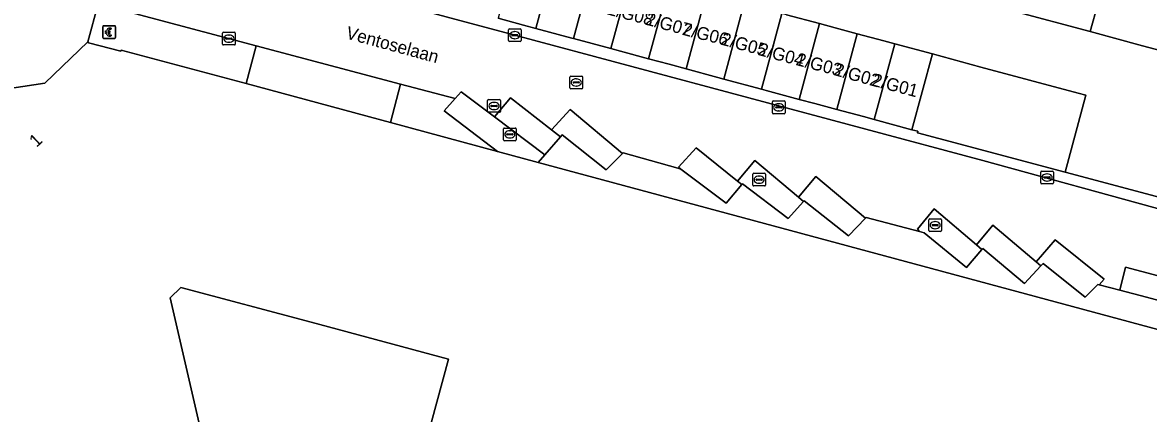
# Model space of a CAD drawing. Extents: x 160675 to 161153, y 383241 to 383714.
# Drawn here: x 160731.8 to 160820, y 383533.4 to 383564 of the extents above; entities that cross this region are included whole.
import ezdxf

# ---------------------------------------------------------------- set-up
doc = ezdxf.new("R2010")
doc.units = 0
for name, color, linetype in [('IMGEO_Betaalautomaat', 7, 'Continuous'), ('IMGEO_Erf', 7, 'Continuous'), ('IMGEO_Kolk', 7, 'Continuous'), ('IMGEO_Openbare_ruimte_label', 7, 'Continuous'), ('IMGEO_Pand', 7, 'Continuous'), ('IMGEO_Pand_nummerreeks', 7, 'Continuous'), ('IMGEO_Parkeervlak_open', 7, 'Continuous'), ('IMGEO_Rijbaan_lokaal_open', 7, 'Continuous'), ('IMGEO_Rioolput', 7, 'Continuous'), ('IMGEO_Voetpad_gesloten', 7, 'Continuous'), ('IMGEO_Voetpad_open', 7, 'Continuous')]:
    doc.layers.add(name, color=color, linetype=linetype)

msp = doc.modelspace()

# ---------------------------------------------------------------- linework, layer by layer
at = {"layer": 'IMGEO_Betaalautomaat'}
for p, q in [((160738.042, 383562.848), (160738.042, 383563.689)), ((160738.042, 383563.689), (160738.042, 383562.848)), ((160738.117, 383563.772), (160738.958, 383563.772)), ((160738.958, 383563.772), (160738.117, 383563.772)), ((160738.704, 383563.577), (160738.687, 383563.477)), ((160739.041, 383563.698), (160739.041, 383562.857)), ((160739.041, 383562.857), (160739.041, 383563.698)), ((160738.967, 383562.773), (160738.126, 383562.773)), ((160738.126, 383562.773), (160738.967, 383562.773)), ((160738.325, 383563.236), (160738.325, 383563.304)), ((160738.446, 383563.304), (160738.446, 383563.236)), ((160738.691, 383563.071), (160738.713, 383562.984))]:
    msp.add_line(p, q, dxfattribs=at)
for points in [[(160738.325, 383563.304), (160738.256, 383563.304), (160738.256, 383563.373), (160738.335, 383563.373)], [(160738.33, 383563.167), (160738.256, 383563.167), (160738.256, 383563.236), (160738.325, 383563.236)], [(160738.457, 383563.373), (160738.604, 383563.373), (160738.604, 383563.304), (160738.446, 383563.304)], [(160738.446, 383563.236), (160738.604, 383563.236), (160738.604, 383563.167), (160738.46, 383563.167)]]:
    msp.add_lwpolyline(points, dxfattribs=at)
for centre, radius, start, end in [((160738.12, 383563.695), 0.0779, 92.4484, 184.28452), ((160738.12, 383563.695), 0.0779, 92.4484, 184.28452), ((160738.618, 383563.297), 0.293, 73.01398, 165.01395), ((160738.964, 383563.695), 0.0779, 2.4484, 94.28452), ((160738.964, 383563.695), 0.0779, 2.4484, 94.28452), ((160738.12, 383562.851), 0.0779, 182.4484, 274.28452), ((160738.12, 383562.851), 0.0779, 182.4484, 274.28452), ((160738.591, 383563.222), 0.267, 191.80956, 297.03891), ((160738.624, 383563.31), 0.179, 69.32359, 159.56827), ((160738.624, 383563.237), 0.179, 202.76249, 291.86925), ((160738.964, 383562.851), 0.0779, 272.4484, 4.28452), ((160738.964, 383562.851), 0.0779, 272.4484, 4.28452)]:
    msp.add_arc(centre, radius, start, end, dxfattribs=at)
at = {"layer": 'IMGEO_Erf'}
for points in [[(160791.615, 383564.635), (160794.187, 383563.942), (160795.419, 383563.61), (160797.134, 383563.148), (160799.224, 383562.585), (160800.081, 383562.354), (160803.028, 383561.56), (160806.833, 383560.536), (160810.637, 383559.511), (160814.441, 383558.486), (160815.054, 383558.321), (160813.434, 383552.307), (160835.666, 383546.367)], [(160821.47, 383561.669), (160819.477, 383562.206), (160815.386, 383563.308), (160809.303, 383564.947)]]:
    msp.add_lwpolyline(points, dxfattribs=at)
msp.add_lwpolyline([(160765.12, 383537.659), (160754.382, 383540.56), (160744.154, 383543.281), (160743.335, 383542.457), (160748.196, 383521.306), (160756.534, 383523.204), (160762.882, 383529.378)], close=True, dxfattribs=at)
at = {"layer": 'IMGEO_Kolk'}
for p, q in [((160769.896, 383563.534), (160770.748, 383563.534)), ((160747.424, 383562.339), (160747.424, 383563.191)), ((160747.499, 383563.265), (160748.351, 383563.265)), ((160747.683, 383562.759), (160747.683, 383562.771)), ((160748.121, 383562.722), (160747.723, 383562.722)), ((160747.726, 383562.808), (160748.124, 383562.808)), ((160747.912, 383563.045), (160747.937, 383563.045)), ((160748.167, 383562.771), (160748.167, 383562.759)), ((160748.425, 383563.191), (160748.425, 383562.339)), ((160769.821, 383562.608), (160769.821, 383563.46)), ((160770.08, 383563.028), (160770.08, 383563.04)), ((160770.518, 383562.991), (160770.12, 383562.991)), ((160770.123, 383563.077), (160770.521, 383563.077)), ((160770.332, 383562.754), (160770.307, 383562.754)), ((160770.309, 383563.314), (160770.334, 383563.314)), ((160770.564, 383563.04), (160770.564, 383563.028)), ((160770.822, 383563.46), (160770.822, 383562.608)), ((160748.351, 383562.265), (160747.499, 383562.265)), ((160747.935, 383562.485), (160747.91, 383562.485)), ((160770.748, 383562.534), (160769.896, 383562.534)), ((160768.194, 383557.064), (160768.194, 383557.916)), ((160768.269, 383557.99), (160769.121, 383557.99)), ((160768.453, 383557.484), (160768.453, 383557.496)), ((160768.891, 383557.447), (160768.493, 383557.447)), ((160768.496, 383557.533), (160768.894, 383557.533)), ((160768.682, 383557.77), (160768.707, 383557.77)), ((160768.937, 383557.496), (160768.937, 383557.484)), ((160769.195, 383557.916), (160769.195, 383557.064)), ((160790.496, 383556.952), (160790.496, 383557.804)), ((160790.571, 383557.878), (160791.423, 383557.878)), ((160790.755, 383557.372), (160790.755, 383557.384)), ((160791.193, 383557.335), (160790.795, 383557.335)), ((160790.798, 383557.421), (160791.196, 383557.421)), ((160790.984, 383557.658), (160791.009, 383557.658)), ((160791.239, 383557.384), (160791.239, 383557.372)), ((160791.497, 383557.804), (160791.497, 383556.952)), ((160769.121, 383556.99), (160768.269, 383556.99)), ((160768.705, 383557.21), (160768.68, 383557.21)), ((160791.423, 383556.878), (160790.571, 383556.878)), ((160791.007, 383557.098), (160790.982, 383557.098)), ((160788.957, 383551.294), (160788.957, 383552.146)), ((160789.032, 383552.22), (160789.884, 383552.22)), ((160789.958, 383552.146), (160789.958, 383551.294)), ((160811.514, 383551.462), (160811.514, 383552.314)), ((160811.589, 383552.388), (160812.441, 383552.388)), ((160812.002, 383552.168), (160812.027, 383552.168)), ((160812.515, 383552.314), (160812.515, 383551.462)), ((160789.884, 383551.22), (160789.032, 383551.22)), ((160789.216, 383551.714), (160789.216, 383551.726)), ((160789.654, 383551.677), (160789.256, 383551.677)), ((160789.259, 383551.763), (160789.657, 383551.763)), ((160789.468, 383551.44), (160789.443, 383551.44)), ((160789.445, 383552), (160789.47, 383552)), ((160789.7, 383551.726), (160789.7, 383551.714)), ((160812.441, 383551.388), (160811.589, 383551.388)), ((160811.773, 383551.882), (160811.773, 383551.894)), ((160812.211, 383551.845), (160811.813, 383551.845)), ((160811.816, 383551.931), (160812.214, 383551.931)), ((160812.025, 383551.608), (160812, 383551.608)), ((160812.257, 383551.894), (160812.257, 383551.882)), ((160802.745, 383547.728), (160802.745, 383548.58)), ((160802.82, 383548.654), (160803.672, 383548.654)), ((160803.746, 383548.58), (160803.746, 383547.728)), ((160803.672, 383547.654), (160802.82, 383547.654)), ((160803.004, 383548.148), (160803.004, 383548.16)), ((160803.442, 383548.111), (160803.044, 383548.111)), ((160803.047, 383548.197), (160803.445, 383548.197)), ((160803.256, 383547.874), (160803.231, 383547.874)), ((160803.233, 383548.434), (160803.258, 383548.434)), ((160803.488, 383548.16), (160803.488, 383548.148))]:
    msp.add_line(p, q, dxfattribs=at)
for points in [[(160769.896, 383563.534), (160770.748, 383563.534)], [(160747.424, 383562.339), (160747.424, 383563.191)], [(160747.499, 383563.265), (160748.351, 383563.265)], [(160748.425, 383563.191), (160748.425, 383562.339)], [(160769.821, 383562.608), (160769.821, 383563.46)], [(160770.822, 383563.46), (160770.822, 383562.608)], [(160748.351, 383562.265), (160747.499, 383562.265)], [(160770.748, 383562.534), (160769.896, 383562.534)], [(160768.194, 383557.064), (160768.194, 383557.916)], [(160768.269, 383557.99), (160769.121, 383557.99)], [(160769.195, 383557.916), (160769.195, 383557.064)], [(160790.496, 383556.952), (160790.496, 383557.804)], [(160790.571, 383557.878), (160791.423, 383557.878)], [(160791.497, 383557.804), (160791.497, 383556.952)], [(160769.121, 383556.99), (160768.269, 383556.99)], [(160791.423, 383556.878), (160790.571, 383556.878)], [(160788.957, 383551.294), (160788.957, 383552.146)], [(160789.032, 383552.22), (160789.884, 383552.22)], [(160789.958, 383552.146), (160789.958, 383551.294)], [(160811.514, 383551.462), (160811.514, 383552.314)], [(160811.589, 383552.388), (160812.441, 383552.388)], [(160812.515, 383552.314), (160812.515, 383551.462)], [(160789.884, 383551.22), (160789.032, 383551.22)], [(160812.441, 383551.388), (160811.589, 383551.388)], [(160802.745, 383547.728), (160802.745, 383548.58)], [(160802.82, 383548.654), (160803.672, 383548.654)], [(160803.746, 383548.58), (160803.746, 383547.728)], [(160803.672, 383547.654), (160802.82, 383547.654)]]:
    msp.add_lwpolyline(points, dxfattribs=at)
for centre, radius, start, end in [((160769.898, 383563.458), 0.0765, 91.55205, 178.44795), ((160769.898, 383563.458), 0.0765, 91.55205, 178.44795), ((160770.746, 383563.458), 0.0765, 1.55205, 88.44795), ((160770.746, 383563.458), 0.0765, 1.55205, 88.44795), ((160747.501, 383563.189), 0.0765, 91.55205, 178.44795), ((160747.501, 383563.189), 0.0765, 91.55205, 178.44795), ((160747.723, 383562.768), 0.0403, 85.87752, 175.75265), ((160747.72, 383562.758), 0.0366, 178.93798, 274.71019), ((160748.124, 383562.765), 0.043, 264.86636, 352.45326), ((160748.128, 383562.77), 0.0386, 1.73085, 96.63898), ((160748.349, 383563.189), 0.0765, 1.55205, 88.44795), ((160748.349, 383563.189), 0.0765, 1.55205, 88.44795), ((160770.12, 383563.037), 0.0403, 85.87752, 175.75265), ((160770.117, 383563.027), 0.0366, 178.93798, 274.71019), ((160770.521, 383563.034), 0.043, 264.86636, 352.45326), ((160770.525, 383563.039), 0.0386, 1.73085, 96.63898), ((160747.501, 383562.341), 0.0765, 181.55205, 268.44795), ((160747.501, 383562.341), 0.0765, 181.55205, 268.44795), ((160748.349, 383562.341), 0.0765, 271.55205, 358.44795), ((160748.349, 383562.341), 0.0765, 271.55205, 358.44795), ((160769.898, 383562.61), 0.0765, 181.55205, 268.44795), ((160769.898, 383562.61), 0.0765, 181.55205, 268.44795), ((160770.746, 383562.61), 0.0765, 271.55205, 358.44795), ((160770.746, 383562.61), 0.0765, 271.55205, 358.44795), ((160768.271, 383557.914), 0.0765, 91.55205, 178.44795), ((160768.271, 383557.914), 0.0765, 91.55205, 178.44795), ((160768.493, 383557.493), 0.0403, 85.87752, 175.75265), ((160768.49, 383557.483), 0.0366, 178.93798, 274.71019), ((160768.894, 383557.49), 0.043, 264.86636, 352.45326), ((160768.898, 383557.495), 0.0386, 1.73085, 96.63898), ((160769.119, 383557.914), 0.0765, 1.55205, 88.44795), ((160769.119, 383557.914), 0.0765, 1.55205, 88.44795), ((160790.573, 383557.802), 0.0765, 91.55205, 178.44795), ((160790.573, 383557.802), 0.0765, 91.55205, 178.44795), ((160790.795, 383557.381), 0.0403, 85.87752, 175.75265), ((160790.792, 383557.371), 0.0366, 178.93798, 274.71019), ((160791.196, 383557.378), 0.043, 264.86636, 352.45326), ((160791.2, 383557.383), 0.0386, 1.73085, 96.63898), ((160791.421, 383557.802), 0.0765, 1.55205, 88.44795), ((160791.421, 383557.802), 0.0765, 1.55205, 88.44795), ((160768.271, 383557.066), 0.0765, 181.55205, 268.44795), ((160768.271, 383557.066), 0.0765, 181.55205, 268.44795), ((160769.119, 383557.066), 0.0765, 271.55205, 358.44795), ((160769.119, 383557.066), 0.0765, 271.55205, 358.44795), ((160790.573, 383556.954), 0.0765, 181.55205, 268.44795), ((160790.573, 383556.954), 0.0765, 181.55205, 268.44795), ((160791.421, 383556.954), 0.0765, 271.55205, 358.44795), ((160791.421, 383556.954), 0.0765, 271.55205, 358.44795), ((160789.034, 383552.144), 0.0765, 91.55205, 178.44795), ((160789.034, 383552.144), 0.0765, 91.55205, 178.44795), ((160789.882, 383552.144), 0.0765, 1.55205, 88.44795), ((160789.882, 383552.144), 0.0765, 1.55205, 88.44795), ((160811.591, 383552.312), 0.0765, 91.55205, 178.44795), ((160811.591, 383552.312), 0.0765, 91.55205, 178.44795), ((160812.439, 383552.312), 0.0765, 1.55205, 88.44795), ((160812.439, 383552.312), 0.0765, 1.55205, 88.44795), ((160789.034, 383551.296), 0.0765, 181.55205, 268.44795), ((160789.034, 383551.296), 0.0765, 181.55205, 268.44795), ((160789.256, 383551.723), 0.0403, 85.87752, 175.75265), ((160789.253, 383551.713), 0.0366, 178.93798, 274.71019), ((160789.657, 383551.72), 0.043, 264.86636, 352.45326), ((160789.661, 383551.725), 0.0386, 1.73085, 96.63898), ((160789.882, 383551.296), 0.0765, 271.55205, 358.44795), ((160789.882, 383551.296), 0.0765, 271.55205, 358.44795), ((160811.591, 383551.464), 0.0765, 181.55205, 268.44795), ((160811.591, 383551.464), 0.0765, 181.55205, 268.44795), ((160811.813, 383551.891), 0.0403, 85.87752, 175.75265), ((160811.81, 383551.881), 0.0366, 178.93798, 274.71019), ((160812.214, 383551.888), 0.043, 264.86636, 352.45326), ((160812.218, 383551.893), 0.0386, 1.73085, 96.63898), ((160812.439, 383551.464), 0.0765, 271.55205, 358.44795), ((160812.439, 383551.464), 0.0765, 271.55205, 358.44795), ((160802.822, 383548.578), 0.0765, 91.55205, 178.44795), ((160802.822, 383548.578), 0.0765, 91.55205, 178.44795), ((160803.67, 383548.578), 0.0765, 1.55205, 88.44795), ((160803.67, 383548.578), 0.0765, 1.55205, 88.44795), ((160802.822, 383547.73), 0.0765, 181.55205, 268.44795), ((160802.822, 383547.73), 0.0765, 181.55205, 268.44795), ((160803.044, 383548.157), 0.0403, 85.87752, 175.75265), ((160803.041, 383548.147), 0.0366, 178.93798, 274.71019), ((160803.445, 383548.154), 0.043, 264.86636, 352.45326), ((160803.449, 383548.159), 0.0386, 1.73085, 96.63898), ((160803.67, 383547.73), 0.0765, 271.55205, 358.44795), ((160803.67, 383547.73), 0.0765, 271.55205, 358.44795)]:
    msp.add_arc(centre, radius, start, end, dxfattribs=at)
for centre, major_axis, ratio, start_param, end_param in [((160747.911, 383562.765), (-0.387, 0.002), 0.722429, 4.712389, 7.853982), ((160747.936, 383562.765), (-0.39, 0.002), 0.717154, 1.570796, 4.712389), ((160770.308, 383563.034), (-0.387, 0.002), 0.722429, 4.712389, 7.853982), ((160770.333, 383563.034), (-0.39, 0.002), 0.717154, 1.570796, 4.712389), ((160768.681, 383557.49), (-0.387, 0.002), 0.722429, 4.712389, 7.853982), ((160768.706, 383557.49), (-0.39, 0.002), 0.717154, 1.570796, 4.712389), ((160790.983, 383557.378), (-0.387, 0.002), 0.722429, 4.712389, 7.853982), ((160791.008, 383557.378), (-0.39, 0.002), 0.717154, 1.570796, 4.712389), ((160812.001, 383551.888), (-0.387, 0.002), 0.722429, 4.712389, 7.853982), ((160812.026, 383551.888), (-0.39, 0.002), 0.717154, 1.570796, 4.712389), ((160789.444, 383551.72), (-0.387, 0.002), 0.722429, 4.712389, 7.853982), ((160789.469, 383551.72), (-0.39, 0.002), 0.717154, 1.570796, 4.712389), ((160803.232, 383548.154), (-0.387, 0.002), 0.722429, 4.712389, 7.853982), ((160803.257, 383548.154), (-0.39, 0.002), 0.717154, 1.570796, 4.712389)]:
    msp.add_ellipse(centre, major_axis=major_axis, ratio=ratio, start_param=start_param, end_param=end_param, dxfattribs=at)
at = {"layer": 'IMGEO_Pand'}
for points in [[(160815.386, 383563.308), (160818.982, 383576.181), (160812.898, 383577.819), (160809.303, 383564.947)], [(160819.477, 383562.206), (160821.47, 383561.669), (160825.065, 383574.542), (160818.982, 383576.181), (160815.386, 383563.308)], [(160773.558, 383569.498), (160772.593, 383569.758), (160770.612, 383570.292), (160769.014, 383564.36), (160770.995, 383563.826), (160771.961, 383563.566)], [(160773.558, 383569.498), (160771.961, 383563.566), (160774.799, 383562.801), (160774.907, 383562.772), (160776.505, 383568.704), (160776.397, 383568.734)], [(160779.452, 383567.911), (160776.505, 383568.704), (160774.907, 383562.772), (160777.854, 383561.978)], [(160779.452, 383567.911), (160777.854, 383561.978), (160778.604, 383561.776), (160780.801, 383561.184), (160782.399, 383567.117), (160780.202, 383567.709)], [(160783.748, 383560.389), (160785.346, 383566.323), (160784.006, 383566.684), (160782.399, 383567.117), (160780.801, 383561.184), (160782.408, 383560.751)], [(160788.293, 383565.529), (160787.811, 383565.659), (160785.346, 383566.323), (160783.748, 383560.389), (160786.212, 383559.725), (160786.695, 383559.595)], [(160788.293, 383565.529), (160786.695, 383559.595), (160789.642, 383558.801), (160791.24, 383564.736)], [(160791.24, 383564.736), (160789.642, 383558.801), (160790.016, 383558.7), (160792.589, 383558.007), (160794.187, 383563.942), (160791.615, 383564.635)], [(160795.536, 383557.213), (160797.134, 383563.148), (160795.419, 383563.61), (160794.187, 383563.942), (160792.589, 383558.007), (160793.821, 383557.675)], [(160795.536, 383557.213), (160797.625, 383556.65), (160798.482, 383556.419), (160800.081, 383562.354), (160799.224, 383562.585), (160797.134, 383563.148)], [(160801.429, 383555.625), (160803.028, 383561.56), (160800.081, 383562.354), (160798.482, 383556.419)], [(160815.054, 383558.321), (160814.441, 383558.486), (160810.637, 383559.511), (160806.833, 383560.536), (160803.028, 383561.56), (160801.429, 383555.625), (160801.89, 383555.501), (160801.862, 383555.394), (160805.207, 383554.502), (160809.014, 383553.486), (160813.434, 383552.307)], [(160762.882, 383529.378), (160756.534, 383523.204), (160748.196, 383521.306), (160743.335, 383542.457), (160744.154, 383543.281), (160754.382, 383540.56), (160765.12, 383537.659)]]:
    msp.add_lwpolyline(points, close=True, dxfattribs=at)
msp.add_lwpolyline([(160824.365, 383538.998), (160772.161, 383553.067), (160768.978, 383553.925), (160760.578, 383556.188), (160749.27, 383559.236), (160739.499, 383561.869), (160739.458, 383561.769), (160736.936, 383562.441), (160736.867, 383562.513), (160734.183, 383559.937), (160733.494, 383559.276), (160728.647, 383558.534), (160727.771, 383553.734), (160724.44, 383550.502), (160724.51, 383550.431), (160725.086, 383547.856), (160724.989, 383547.833), (160725.173, 383547.028), (160737.721, 383492.328)], dxfattribs=at)
at = {"layer": 'IMGEO_Parkeervlak_open'}
for points in [[(160765.643, 383558.073), (160761.377, 383559.203), (160760.578, 383556.188), (160768.978, 383553.925), (160764.787, 383557.113)], [(160768.731, 383556.624), (160766.112, 383558.599), (160765.643, 383558.073), (160764.787, 383557.113), (160768.978, 383553.925), (160772.161, 383553.067), (160772.669, 383553.654)], [(160768.731, 383556.624), (160772.669, 383553.654), (160773.903, 383555.08), (160773.2, 383555.625), (160769.987, 383558.116)], [(160773.2, 383555.625), (160773.903, 383555.08), (160774.032, 383555.228), (160777.477, 383552.475), (160778.768, 383553.77), (160774.65, 383557.216)], [(160783.322, 383552.547), (160786.884, 383549.861), (160788.11, 383551.327), (160787.775, 383551.597), (160784.524, 383554.209), (160783.154, 383552.689)], [(160792.94, 383550.004), (160792.542, 383550.339), (160789.123, 383553.211), (160787.775, 383551.597), (160788.11, 383551.327), (160788.159, 383551.385), (160791.74, 383548.675)], [(160792.542, 383550.339), (160792.94, 383550.004), (160792.987, 383550.057), (160796.452, 383547.324), (160797.791, 383548.706), (160793.905, 383551.971)], [(160802.032, 383547.656), (160802.399, 383547.561), (160805.699, 383544.831), (160806.916, 383546.239), (160806.478, 383546.613), (160803.172, 383549.44), (160801.852, 383547.834)], [(160806.478, 383546.613), (160806.916, 383546.239), (160806.981, 383546.315), (160810.235, 383543.592), (160811.537, 383544.97), (160811.172, 383545.277), (160807.757, 383548.146)], [(160811.172, 383545.277), (160811.537, 383544.97), (160811.702, 383545.144), (160814.986, 383542.501), (160815.994, 383543.513), (160816.082, 383543.49), (160816.499, 383543.92), (160812.635, 383547.01)], [(160818.163, 383544.869), (160817.716, 383543.056), (160819.812, 383542.5), (160827.531, 383540.452), (160828.009, 383542.256)]]:
    msp.add_lwpolyline(points, close=True, dxfattribs=at)
at = {"layer": 'IMGEO_Rijbaan_lokaal_open'}
for points in [[(160821.426, 383549.252), (160806.97, 383553.205), (160770.322, 383563.034), (160748.417, 383568.908)], [(160737.693, 383565.476), (160750.056, 383562.202), (160761.377, 383559.203), (160765.643, 383558.073), (160766.112, 383558.599), (160768.731, 383556.624), (160769.987, 383558.116), (160773.2, 383555.625), (160774.65, 383557.216), (160778.768, 383553.77), (160778.807, 383553.809), (160783.095, 383552.611), (160783.322, 383552.547), (160783.154, 383552.689), (160784.524, 383554.209), (160787.775, 383551.597), (160789.123, 383553.211), (160792.542, 383550.339), (160793.905, 383551.971), (160797.791, 383548.706), (160797.831, 383548.748), (160802.032, 383547.656), (160801.852, 383547.834), (160803.172, 383549.44), (160806.478, 383546.613), (160807.757, 383548.146), (160811.172, 383545.277), (160812.635, 383547.01), (160816.499, 383543.92), (160816.082, 383543.49), (160817.716, 383543.056), (160818.163, 383544.869), (160828.009, 383542.256)]]:
    msp.add_lwpolyline(points, dxfattribs=at)
at = {"layer": 'IMGEO_Rioolput'}
for p, q in [((160774.635, 383558.904), (160774.635, 383559.756)), ((160774.71, 383559.83), (160775.562, 383559.83)), ((160774.894, 383559.324), (160774.894, 383559.336)), ((160775.332, 383559.287), (160774.934, 383559.287)), ((160774.937, 383559.373), (160775.335, 383559.373)), ((160775.123, 383559.61), (160775.148, 383559.61)), ((160775.378, 383559.336), (160775.378, 383559.324)), ((160775.636, 383559.756), (160775.636, 383558.904)), ((160775.562, 383558.83), (160774.71, 383558.83)), ((160775.146, 383559.05), (160775.121, 383559.05)), ((160769.433, 383554.835), (160769.433, 383555.687)), ((160769.508, 383555.761), (160770.36, 383555.761)), ((160770.434, 383555.687), (160770.434, 383554.835)), ((160770.36, 383554.761), (160769.508, 383554.761)), ((160769.692, 383555.255), (160769.692, 383555.267)), ((160770.13, 383555.218), (160769.732, 383555.218)), ((160769.735, 383555.304), (160770.133, 383555.304)), ((160769.944, 383554.981), (160769.919, 383554.981)), ((160769.921, 383555.541), (160769.946, 383555.541)), ((160770.176, 383555.267), (160770.176, 383555.255))]:
    msp.add_line(p, q, dxfattribs=at)
for points in [[(160774.635, 383558.904), (160774.635, 383559.756)], [(160774.71, 383559.83), (160775.562, 383559.83)], [(160775.636, 383559.756), (160775.636, 383558.904)], [(160775.562, 383558.83), (160774.71, 383558.83)], [(160769.433, 383554.835), (160769.433, 383555.687)], [(160769.508, 383555.761), (160770.36, 383555.761)], [(160770.434, 383555.687), (160770.434, 383554.835)], [(160770.36, 383554.761), (160769.508, 383554.761)]]:
    msp.add_lwpolyline(points, dxfattribs=at)
for centre, radius, start, end in [((160774.712, 383559.754), 0.0765, 91.55205, 178.44795), ((160774.712, 383559.754), 0.0765, 91.55205, 178.44795), ((160774.934, 383559.333), 0.0403, 85.87752, 175.75265), ((160774.931, 383559.323), 0.0366, 178.93798, 274.71019), ((160775.335, 383559.33), 0.043, 264.86636, 352.45326), ((160775.339, 383559.335), 0.0386, 1.73085, 96.63898), ((160775.56, 383559.754), 0.0765, 1.55205, 88.44795), ((160775.56, 383559.754), 0.0765, 1.55205, 88.44795), ((160774.712, 383558.906), 0.0765, 181.55205, 268.44795), ((160774.712, 383558.906), 0.0765, 181.55205, 268.44795), ((160775.56, 383558.906), 0.0765, 271.55205, 358.44795), ((160775.56, 383558.906), 0.0765, 271.55205, 358.44795), ((160769.51, 383555.685), 0.0765, 91.55205, 178.44795), ((160769.51, 383555.685), 0.0765, 91.55205, 178.44795), ((160770.358, 383555.685), 0.0765, 1.55205, 88.44795), ((160770.358, 383555.685), 0.0765, 1.55205, 88.44795), ((160769.51, 383554.837), 0.0765, 181.55205, 268.44795), ((160769.51, 383554.837), 0.0765, 181.55205, 268.44795), ((160769.732, 383555.264), 0.0403, 85.87752, 175.75265), ((160769.729, 383555.254), 0.0366, 178.93798, 274.71019), ((160770.133, 383555.261), 0.043, 264.86636, 352.45326), ((160770.137, 383555.266), 0.0386, 1.73085, 96.63898), ((160770.358, 383554.837), 0.0765, 271.55205, 358.44795), ((160770.358, 383554.837), 0.0765, 271.55205, 358.44795)]:
    msp.add_arc(centre, radius, start, end, dxfattribs=at)
for centre, major_axis, ratio, start_param, end_param in [((160775.122, 383559.33), (-0.387, 0.002), 0.722429, 4.712389, 7.853982), ((160775.147, 383559.33), (-0.39, 0.002), 0.717154, 1.570796, 4.712389), ((160769.92, 383555.261), (-0.387, 0.002), 0.722429, 4.712389, 7.853982), ((160769.945, 383555.261), (-0.39, 0.002), 0.717154, 1.570796, 4.712389)]:
    msp.add_ellipse(centre, major_axis=major_axis, ratio=ratio, start_param=start_param, end_param=end_param, dxfattribs=at)
at = {"layer": 'IMGEO_Voetpad_gesloten'}
msp.add_lwpolyline([(160750.056, 383562.202), (160749.27, 383559.236), (160760.578, 383556.188), (160761.377, 383559.203)], close=True, dxfattribs=at)
at = {"layer": 'IMGEO_Voetpad_open'}
for points in [[(160748.417, 383568.908), (160770.322, 383563.034), (160806.97, 383553.205), (160821.426, 383549.252)], [(160728.647, 383558.534), (160733.494, 383559.276), (160734.183, 383559.937), (160736.867, 383562.513), (160737.693, 383565.476), (160737.403, 383565.553), (160735.719, 383566.037), (160731.259, 383566.644)], [(160835.666, 383546.367), (160813.434, 383552.307), (160809.014, 383553.486), (160805.207, 383554.502), (160801.862, 383555.394), (160801.89, 383555.501), (160801.429, 383555.625), (160798.482, 383556.419), (160797.625, 383556.65), (160795.536, 383557.213), (160793.821, 383557.675), (160792.589, 383558.007), (160790.016, 383558.7), (160789.642, 383558.801), (160786.695, 383559.595), (160786.212, 383559.725), (160783.748, 383560.389), (160782.408, 383560.751), (160780.801, 383561.184), (160778.604, 383561.776), (160777.854, 383561.978), (160774.907, 383562.772), (160774.799, 383562.801), (160771.961, 383563.566), (160770.995, 383563.826), (160769.014, 383564.36)], [(160827.531, 383540.452), (160819.812, 383542.5), (160817.716, 383543.056), (160816.082, 383543.49), (160815.994, 383543.513), (160814.986, 383542.501), (160811.702, 383545.144), (160811.537, 383544.97), (160810.235, 383543.592), (160806.981, 383546.315), (160806.916, 383546.239), (160805.699, 383544.831), (160802.399, 383547.561), (160802.032, 383547.656), (160797.831, 383548.748), (160797.791, 383548.706), (160796.452, 383547.324), (160792.987, 383550.057), (160792.94, 383550.004), (160791.74, 383548.675), (160788.159, 383551.385), (160788.11, 383551.327), (160786.884, 383549.861), (160783.322, 383552.547), (160783.095, 383552.611), (160778.807, 383553.809), (160778.768, 383553.77), (160777.477, 383552.475), (160774.032, 383555.228), (160773.903, 383555.08), (160772.669, 383553.654), (160772.161, 383553.067), (160824.365, 383538.998)]]:
    msp.add_lwpolyline(points, dxfattribs=at)
msp.add_lwpolyline([(160736.867, 383562.513), (160736.936, 383562.441), (160739.458, 383561.769), (160739.499, 383561.869), (160749.27, 383559.236), (160750.056, 383562.202), (160737.693, 383565.476)], close=True, dxfattribs=at)

# ---------------------------------------------------------------- texts
at = {"layer": 'IMGEO_Openbare_ruimte_label'}
msp.add_text('Ventoselaan', height=1, rotation=344.69968, dxfattribs=at).set_placement((160757.027, 383562.787))
at = {"layer": 'IMGEO_Pand_nummerreeks'}
for s, rotation, p in [('2/G08', 345.22038, (160777.504, 383564.669)), ('2/G07', 344.77532, (160780.49, 383563.879)), ('2/G06', 345.87413, (160783.374, 383563.074)), ('2/G05', 344.77532, (160786.394, 383562.311)), ('2/G04', 345.02427, (160789.309, 383561.494)), ('2/G03', 345.32321, (160792.278, 383560.709)), ('2/G02', 344.32888, (160795.249, 383559.921)), ('2/G01', 345.12834, (160798.231, 383559.096)), ('1', 43.45885, (160732.855, 383554.194))]:
    msp.add_text(s, height=1, rotation=rotation, dxfattribs=at).set_placement(p)

doc.saveas('drawing.dxf')
